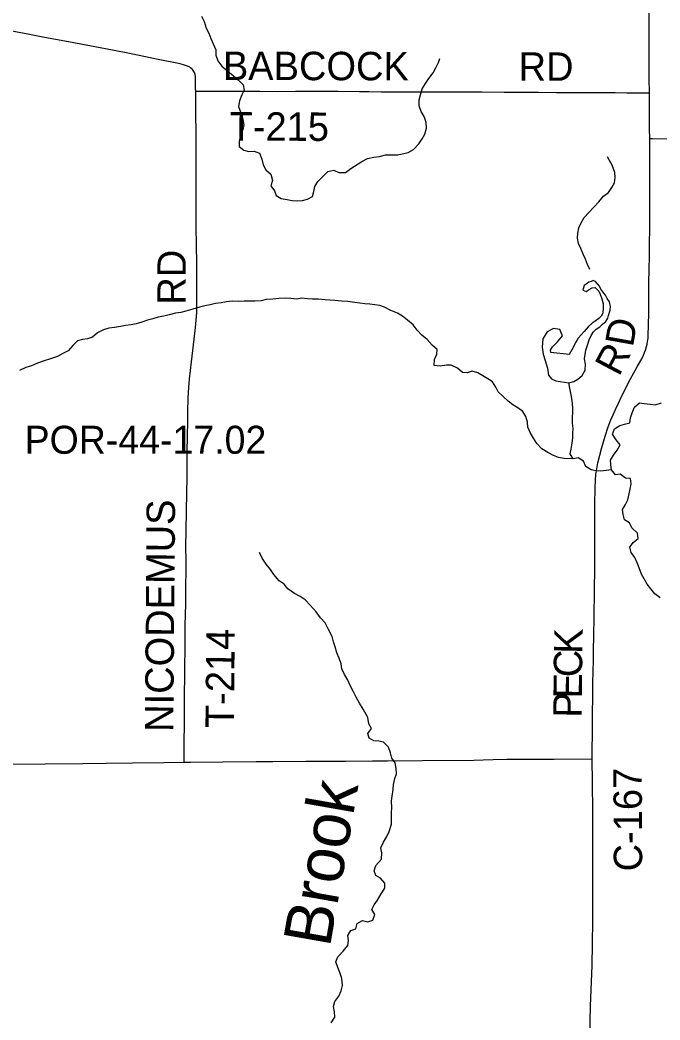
# Model space of a CAD drawing. Extents: x 0 to 34, y 0 to 22.
# Drawn here: x 4.121 to 7.317, y 9.413 to 14.409 of the extents above; entities that cross this region are included whole.
import ezdxf

# ---------------------------------------------------------------- set-up
doc = ezdxf.new("R2010")
doc.units = 0
for name, color, linetype in [('GM_X_County_Road', 7, 'Continuous'), ('GM_X_County_Road_Text', 7, 'Continuous'), ('GM_X_Minor_Lake', 7, 'Continuous'), ('GM_X_Minor_River', 7, 'Continuous'), ('GM_X_Minor_River_Text', 7, 'Continuous'), ('GM_X_Township_Road', 7, 'Continuous'), ('GM_X_Township_Road_Text', 7, 'Continuous'), ('SH_Text', 7, 'Continuous')]:
    doc.layers.add(name, color=color, linetype=linetype)

msp = doc.modelspace()

# ---------------------------------------------------------------- linework, layer by layer
at = {"layer": 'GM_X_County_Road'}
for points in [[(7.2639, 14.0452), (7.2636, 14.118), (7.2636, 14.1506), (7.2636, 14.1614), (7.2635, 14.1723), (7.2635, 14.2189), (7.2637, 14.2521), (7.2634, 14.3326), (7.2634, 14.3957), (7.2634, 14.4535)], [(7.2657, 13.8168), (7.2651, 13.8652), (7.2652, 13.896), (7.2645, 13.9254), (7.2643, 13.9627), (7.2641, 14.0125), (7.2641, 14.0311), (7.2639, 14.0452)], [(6.9784, 10.7179), (6.979, 10.7631), (6.9799, 10.8448), (6.9807, 10.9383), (6.9814, 11.0346), (6.9825, 11.0983), (6.9837, 11.1542), (6.9848, 11.2069), (6.985, 11.238), (6.9851, 11.2659), (6.9862, 11.3281), (6.988, 11.4306), (6.9886, 11.4601), (6.9897, 11.5237), (6.99, 11.5579), (6.9905, 11.5951), (6.9909, 11.6339), (6.9915, 11.7178), (6.992, 11.783), (6.9921, 11.8436), (6.9919, 11.87), (6.9922, 11.9041), (6.9924, 11.9662), (6.9924, 11.9924), (6.9925, 12.0186), (6.9927, 12.0424), (6.9933, 12.0706), (6.995, 12.1103), (6.9975, 12.1395), (7.0012, 12.1668), (7.0065, 12.1971), (7.016, 12.2347), (7.0265, 12.2729), (7.044, 12.3297), (7.0591, 12.3769), (7.0722, 12.4113), (7.0829, 12.4372), (7.0945, 12.4635), (7.1093, 12.4943), (7.1255, 12.5283), (7.1682, 12.6129), (7.2046, 12.6793), (7.226, 12.717), (7.2346, 12.735), (7.2398, 12.7472), (7.2446, 12.76), (7.2502, 12.7775), (7.253, 12.7899), (7.2554, 12.8026), (7.2566, 12.8118), (7.2573, 12.8193), (7.2578, 12.8258), (7.2581, 12.8322), (7.2583, 12.838), (7.2587, 12.8465), (7.2594, 12.8713), (7.2602, 12.9007), (7.2607, 12.9303), (7.2611, 12.9622), (7.2607, 13.0053), (7.2611, 13.0492), (7.2622, 13.0961), (7.2634, 13.1637), (7.2641, 13.2281), (7.2649, 13.2875), (7.2657, 13.3708), (7.2657, 13.4382), (7.266, 13.4904), (7.2662, 13.5367), (7.2658, 13.6189), (7.2663, 13.6648), (7.2663, 13.7534), (7.2657, 13.814), (7.2657, 13.8168)], [(2.8188, 10.6798), (2.8697, 10.68), (3.2053, 10.6832), (3.2658, 10.6842), (3.3326, 10.6853), (3.5691, 10.6851), (3.6275, 10.6855), (3.7629, 10.6872), (3.8468, 10.6884), (4.0192, 10.6911), (4.246, 10.6928), (4.4341, 10.6952), (4.5506, 10.6961), (4.6827, 10.6977), (4.8396, 10.6995), (4.9411, 10.701)], [(4.9411, 10.701), (4.9717, 10.7015), (5.1333, 10.703), (5.2996, 10.7041), (5.3835, 10.7043), (5.5482, 10.7056), (5.747, 10.7068), (5.8806, 10.7075), (5.9567, 10.708), (6.1291, 10.7094), (6.3877, 10.7118), (6.4333, 10.7127), (6.4833, 10.714), (6.5517, 10.7158), (6.6978, 10.717), (6.7879, 10.717), (6.9784, 10.7179)], [(6.9667, 9.3286), (6.9706, 9.4838), (6.973, 9.5614), (6.9765, 9.6458), (6.9777, 9.6832), (6.9805, 9.7958), (6.9822, 9.9093), (6.9822, 9.9403), (6.9822, 10.0692), (6.9815, 10.136), (6.9814, 10.1889), (6.9815, 10.2308), (6.9811, 10.3815), (6.981, 10.4561), (6.9798, 10.6005), (6.9784, 10.7179)]]:
    msp.add_lwpolyline(points, dxfattribs=at)
at = {"layer": 'GM_X_Minor_Lake'}
msp.add_line((6.7964, 12.6065), (6.8619, 12.5958), dxfattribs=at)
msp.add_lwpolyline([(6.8619, 12.5958), (6.8864, 12.6037), (6.9071, 12.6144), (6.9287, 12.6336), (6.9435, 12.6594), (6.9451, 12.6898), (6.94, 12.7164), (6.9471, 12.7592), (6.9554, 12.7849), (6.9636, 12.8106), (6.9738, 12.8335), (6.9849, 12.8508), (6.998, 12.8651), (7.0159, 12.8758), (7.03, 12.8893), (7.0468, 12.9037), (7.0571, 12.919), (7.0598, 12.9333), (7.068, 12.9599), (7.0697, 12.978), (7.0657, 13.0007), (7.0532, 13.0177), (7.0454, 13.0337), (7.031, 13.0516), (7.0214, 13.0638), (7.0155, 13.0789), (7.005, 13.0912), (6.9944, 13.1034), (6.984, 13.108), (6.9727, 13.1031), (6.9613, 13.0992), (6.9529, 13.0934), (6.9379, 13.0828), (6.9324, 13.0599), (6.9486, 13.0535), (6.9627, 13.0622), (6.9787, 13.0709), (6.9929, 13.073), (7.012, 13.0542), (7.0188, 13.0391), (7.0267, 13.0155), (7.0336, 12.9909), (7.0329, 12.97), (7.0312, 12.9443), (7.0238, 12.93), (7.0117, 12.9175), (6.9929, 12.904), (6.9778, 12.8953), (6.9581, 12.877), (6.9385, 12.8531), (6.9086, 12.8204), (6.8956, 12.7956), (6.877, 12.7612), (6.8641, 12.7373), (6.7721, 12.7486), (6.771, 12.759), (6.7803, 12.7762), (6.8056, 12.8021), (6.8299, 12.8309), (6.8172, 12.8621), (6.7859, 12.8684), (6.7539, 12.8509), (6.7316, 12.8155), (6.7282, 12.7746), (6.7334, 12.7405), (6.7432, 12.7084), (6.7559, 12.6705), (6.7601, 12.6355), (6.7755, 12.6167), (6.7964, 12.6065)], dxfattribs=at)
at = {"layer": 'GM_X_Minor_River'}
for points in [[(5.0273, 14.4276), (5.0399, 14.4021), (5.0497, 14.369), (5.0632, 14.3435), (5.074, 14.317), (5.0856, 14.2896), (5.0983, 14.2603), (5.0995, 14.2328), (5.1093, 14.2054), (5.1285, 14.1781), (5.1591, 14.1538), (5.1858, 14.1323), (5.2107, 14.1098), (5.2347, 14.0854), (5.2397, 14.0588), (5.2286, 14.035), (5.2166, 14.0054), (5.2112, 13.9778), (5.2239, 13.9447), (5.2327, 13.9201), (5.2378, 13.886), (5.2334, 13.8622), (5.2214, 13.8336), (5.2151, 13.8041), (5.2154, 13.7775), (5.2392, 13.7588), (5.263, 13.7525), (5.2904, 13.7537), (5.317, 13.7436), (5.3278, 13.7133), (5.3348, 13.6849), (5.3483, 13.6604), (5.3731, 13.6389), (5.3811, 13.6076), (5.3738, 13.581), (5.3911, 13.5565), (5.4008, 13.5319), (5.4247, 13.517), (5.455, 13.5117), (5.4797, 13.5072), (5.5062, 13.5056), (5.5318, 13.5068), (5.5563, 13.5138), (5.5808, 13.5274), (5.589, 13.5531), (5.5925, 13.5778), (5.6074, 13.6027), (5.6327, 13.6267), (5.658, 13.6517), (5.6873, 13.6587), (5.713, 13.6466), (5.7461, 13.648), (5.7733, 13.6673), (5.8279, 13.7021), (5.857, 13.7176), (5.8873, 13.7246), (5.9166, 13.7268), (5.9459, 13.7357), (5.9799, 13.7352), (6.0083, 13.7355), (6.0593, 13.7475), (6.0857, 13.763), (6.1119, 13.7899), (6.1287, 13.8148), (6.1426, 13.8396), (6.1517, 13.8692), (6.1486, 13.8976)], [(6.1486, 13.8976), (6.1388, 13.9269), (6.1243, 13.9524), (6.1145, 13.9798), (6.1151, 14.0102), (6.1205, 14.0359), (6.1287, 14.0645), (6.1464, 14.0912), (6.1632, 14.1171), (6.1837, 14.1448), (6.1967, 14.1697), (6.2115, 14.1964), (6.2179, 14.2165)], [(6.9663, 13.1619), (6.9547, 13.1884), (6.9449, 13.2139), (6.9333, 13.2394), (6.9216, 13.2677), (6.9099, 13.2932), (6.9059, 13.3197), (6.9075, 13.3435), (6.9119, 13.3701), (6.923, 13.3959), (6.9379, 13.4227), (6.9613, 13.4467), (6.9865, 13.4735), (7.0118, 13.5014), (7.0351, 13.5292), (7.0596, 13.5475), (7.0763, 13.5724), (7.0893, 13.5963), (7.0928, 13.6229), (7.0916, 13.6476), (7.0779, 13.6835), (7.0654, 13.708), (7.0547, 13.7259)], [(7.075, 12.1617), (7.0476, 12.1585), (7.0211, 12.1553), (6.9965, 12.1569), (6.9727, 12.1614), (6.946, 12.1791), (6.9353, 12.2046), (6.9086, 12.2224), (6.8831, 12.2173), (6.8377, 12.2187), (6.8101, 12.224), (6.7845, 12.2332), (6.7568, 12.2481), (6.7273, 12.2667), (6.7024, 12.293), (6.686, 12.3194), (6.6696, 12.3449), (6.6569, 12.3751), (6.6557, 12.4007), (6.6478, 12.4281), (6.6315, 12.4526), (6.6076, 12.4723), (6.5828, 12.4872), (6.5589, 12.505), (6.534, 12.5274), (6.5092, 12.5509), (6.4966, 12.5754), (6.4811, 12.6018), (6.4573, 12.6167), (6.4325, 12.6316), (6.4068, 12.6456), (6.3792, 12.6547), (6.3547, 12.6469), (6.3301, 12.6475), (6.3062, 12.6691), (6.2738, 12.6839), (6.2501, 12.6855), (6.2199, 12.6795), (6.1886, 12.6829), (6.1902, 12.7133), (6.2022, 12.7391), (6.2038, 12.7628), (6.1789, 12.7853), (6.155, 12.8135), (6.1282, 12.8341), (6.1042, 12.8604), (6.0841, 12.8858), (6.0554, 12.9101), (6.0306, 12.9298), (6.0067, 12.9447), (5.9725, 12.9585), (5.9411, 12.9743), (5.9173, 12.9826), (5.8936, 12.9861), (5.868, 12.9896), (5.8424, 12.9912), (5.7931, 12.9982), (5.758, 13.0025), (5.7267, 13.005), (5.6936, 13.0075), (5.6689, 13.01), (5.6443, 13.0107), (5.6111, 13.0151), (5.5808, 13.0147), (5.5571, 13.0163), (5.5277, 13.0198), (5.5032, 13.0147), (5.4738, 13.0172), (5.4454, 13.0188), (5.4132, 13.0175), (5.3829, 13.0143), (5.3498, 13.012), (5.3253, 13.006), (5.2931, 13.0047), (5.2401, 13.0041), (5.2117, 13.0028), (5.1823, 13.0043), (5.152, 13.0011), (5.1246, 12.9961), (5.0972, 12.9929), (5.0708, 12.9869), (5.0434, 12.9809), (5.0179, 12.9749), (4.9839, 12.9641), (4.949, 12.9551), (4.9244, 12.9482), (4.898, 12.9441), (4.8649, 12.9361), (4.8385, 12.9301), (4.8101, 12.9241), (4.7847, 12.9162), (4.7573, 12.9092), (4.7299, 12.8994), (4.7016, 12.8905), (4.6761, 12.8855), (4.6468, 12.8823), (4.6222, 12.8782), (4.5929, 12.8731), (4.5646, 12.869), (4.5372, 12.862), (4.508, 12.8465)], [(4.508, 12.8465), (4.4827, 12.8253), (4.4572, 12.8155), (4.4326, 12.8124), (4.4071, 12.8064), (4.3837, 12.7824), (4.3604, 12.7565), (4.3349, 12.7429), (4.3086, 12.7274), (4.2727, 12.7165), (4.2416, 12.7067), (4.2086, 12.6949), (4.1775, 12.6822), (4.1501, 12.6733), (4.1181, 12.6587)], [(6.8831, 12.2173), (6.8677, 12.2418), (6.8731, 12.2656), (6.8785, 12.2951), (6.882, 12.3198), (6.8826, 12.3445), (6.8833, 12.3683), (6.8802, 12.3948), (6.8799, 12.4242), (6.8815, 12.448), (6.8812, 12.4717), (6.8789, 12.5077), (6.8739, 12.5371), (6.8689, 12.5617), (6.8619, 12.5958)], [(7.3179, 11.5228), (7.2912, 11.5415), (7.272, 11.5669), (7.2537, 11.5913), (7.2373, 11.6168), (7.2247, 11.6413), (7.213, 11.6715), (7.2033, 11.698), (7.1907, 11.7235), (7.1734, 11.7489), (7.1664, 11.7754), (7.1832, 11.7993), (7.2086, 11.8186), (7.2045, 11.8461), (7.1767, 11.8724), (7.1651, 11.8969), (7.1403, 11.9128), (7.1324, 11.9383), (7.1302, 11.9639), (7.1451, 11.9878), (7.1562, 12.0126), (7.1625, 12.0412), (7.1679, 12.065), (7.1733, 12.0916), (7.1692, 12.1191), (7.1446, 12.1207), (7.1188, 12.1394), (7.0942, 12.1362), (7.075, 12.1617), (7.0719, 12.1863), (7.0707, 12.21), (7.0855, 12.2358), (7.1033, 12.2607), (7.1181, 12.2865), (7.0979, 12.3119), (7.0797, 12.3392), (7.0898, 12.3659), (7.1161, 12.3833), (7.1406, 12.3893), (7.1661, 12.3972), (7.1696, 12.421), (7.1788, 12.4458), (7.1899, 12.4744), (7.2142, 12.4965), (7.238, 12.493), (7.2673, 12.4905), (7.293, 12.486), (7.325, 12.4968)], [(5.7179, 9.6503), (5.7082, 9.6758), (5.6974, 9.7041), (5.7076, 9.7289), (5.7347, 9.7568), (5.7581, 9.7855), (5.7606, 9.8102), (5.7584, 9.8358), (5.7724, 9.8607), (5.7979, 9.8686), (5.8051, 9.8952), (5.8305, 9.9098), (5.8571, 9.9034), (5.8826, 9.9123), (5.8936, 9.9399), (5.8782, 9.9644), (5.8902, 9.9883), (5.907, 10.0122), (5.9237, 10.0428), (5.9423, 10.0715), (5.942, 10.0961), (5.9219, 10.1215), (5.8981, 10.1345), (5.8893, 10.1591), (5.8984, 10.1848), (5.9255, 10.2174), (5.9271, 10.2488), (5.923, 10.2734), (5.9369, 10.3011), (5.9536, 10.3298), (5.9637, 10.3555), (5.9756, 10.3917), (5.9763, 10.4202), (5.9769, 10.4496), (5.9785, 10.4734), (5.9762, 10.5075), (5.9797, 10.5322), (5.9851, 10.5646), (5.9867, 10.5902), (5.993, 10.6197), (6.0012, 10.6435), (5.999, 10.6692), (5.9949, 10.6976), (5.9785, 10.7221), (5.9707, 10.7486), (5.9609, 10.7769), (5.9369, 10.8013), (5.9132, 10.8067), (5.8886, 10.8083), (5.8648, 10.8204), (5.8579, 10.845), (5.8765, 10.8689), (5.8621, 10.8935), (5.8579, 10.9247), (5.8347, 10.9662), (5.8164, 10.9954), (5.799, 11.0266), (5.7864, 11.052), (5.7709, 11.0813), (5.7564, 11.1143), (5.7409, 11.1398), (5.7283, 11.1672), (5.7252, 11.1928), (5.7154, 11.2202), (5.7028, 11.2476), (5.6949, 11.2769), (5.6861, 11.3024), (5.6792, 11.3289), (5.6617, 11.3648), (5.6443, 11.3969), (5.6213, 11.4232), (5.6001, 11.4523), (5.5695, 11.4852), (5.5446, 11.5125), (5.5198, 11.5283), (5.4921, 11.5432), (5.4587, 11.5665), (5.4395, 11.591), (5.4147, 11.6078), (5.3888, 11.6388), (5.3715, 11.6633), (5.3494, 11.6905), (5.3301, 11.7197), (5.3175, 11.749), (5.3185, 11.7471)], [(5.6753, 9.3983), (5.693, 9.4279), (5.6918, 9.4545), (5.6858, 9.481), (5.6931, 9.5048), (5.7126, 9.5325), (5.7247, 9.5583), (5.731, 9.5859), (5.7287, 9.62), (5.7179, 9.6503)]]:
    msp.add_lwpolyline(points, dxfattribs=at)
at = {"layer": 'GM_X_Township_Road'}
for points in [[(4.9984, 14.0529), (4.9978, 14.0681), (4.9972, 14.096), (4.9973, 14.1039), (4.9967, 14.1291), (4.9949, 14.137), (4.9923, 14.1462), (4.9858, 14.1573), (4.9829, 14.1611), (4.9746, 14.1688), (4.9681, 14.1733), (4.9567, 14.1791), (4.9417, 14.1842), (4.9204, 14.1894), (4.8108, 14.2123), (4.6753, 14.24), (4.5821, 14.2577), (4.4938, 14.2755), (4.3625, 14.3005), (4.2433, 14.3223), (4.1593, 14.338), (4.0449, 14.3593), (3.9991, 14.3678), (3.9756, 14.3721)], [(4.9411, 10.701), (4.9411, 10.7182), (4.9411, 10.817), (4.9421, 10.8744), (4.9424, 10.9148), (4.9426, 10.9521), (4.9424, 11.0159), (4.9441, 11.1557), (4.9441, 11.2008), (4.9449, 11.2473), (4.9458, 11.3281), (4.9463, 11.384), (4.9482, 11.4928), (4.9491, 11.5845), (4.9498, 11.6544), (4.95, 11.7072), (4.9493, 11.7787), (4.9502, 11.8563), (4.9522, 11.9588), (4.9549, 12.1267), (4.956, 12.2479), (4.9574, 12.3333), (4.9588, 12.4016), (4.959, 12.4514), (4.961, 12.5212), (4.9635, 12.5724), (4.9669, 12.6141), (4.9764, 12.7021), (4.9905, 12.8146), (4.9977, 12.8733), (5.0012, 12.9089), (5.0034, 12.9478), (5.004, 12.9898), (5.0042, 13.0628), (5.0043, 13.1141), (5.0042, 13.1918), (5.0026, 13.2851), (5.0013, 13.3752), (5, 13.4746), (5.0002, 13.546), (4.9998, 13.6362), (5.0002, 13.7387), (5.0003, 13.8226), (5.0004, 13.8568), (4.9994, 13.9283), (4.9993, 13.992), (4.9989, 14.0386), (4.9984, 14.0529)], [(4.9984, 14.0529), (5.0111, 14.053), (5.037, 14.0534), (5.1363, 14.0537), (5.219, 14.0533), (5.3193, 14.0533), (5.4047, 14.0527), (5.4964, 14.053), (5.6222, 14.0535), (5.7092, 14.0532), (5.8164, 14.0524), (5.8645, 14.0516), (5.9251, 14.0507), (5.9811, 14.051), (6.0898, 14.0507), (6.1411, 14.0509), (6.1722, 14.0511), (6.305, 14.0506), (6.4267, 14.0499), (6.5391, 14.049), (6.621, 14.0479), (6.711, 14.0479), (6.7995, 14.0471), (6.9315, 14.0468), (6.963, 14.0465), (7.0291, 14.0465), (7.093, 14.0463), (7.1517, 14.0461), (7.2518, 14.0453), (7.2639, 14.0452)], [(7.2657, 13.8168), (7.2805, 13.8167), (7.4566, 13.8147), (7.7313, 13.8118), (7.7496, 13.8102), (7.7675, 13.8064), (7.776, 13.8033), (7.7858, 13.7991), (7.8003, 13.7906), (7.8131, 13.7819), (7.828, 13.771), (7.8358, 13.7647)]]:
    msp.add_lwpolyline(points, dxfattribs=at)

# ---------------------------------------------------------------- texts
at = {"layer": 'GM_X_County_Road_Text'}
for s, height, rotation, p in [('D', 0.142, 79.8842, (7.1815, 12.7714)), ('R', 0.142, 62.1013, (7.1116, 12.6237)), ('K', 0.142, 88.7286, (6.9291, 11.2413)), ('C', 0.142, 89.395, (6.9279, 11.1251)), ('E', 0.142, 89.4129, (6.9268, 11.0189)), ('P', 0.142, 89.4156, (6.9259, 10.9231)), ('C-167', 0.14205, 90.2751, (7.2285, 10.156))]:
    msp.add_text(s, height=height, rotation=rotation, dxfattribs=at).set_placement(p)
at = {"layer": 'GM_X_Minor_River_Text'}
msp.add_text('Brook', height=0.23682, rotation=79.9852, dxfattribs=at).set_placement((5.6677, 9.7717))
at = {"layer": 'GM_X_Township_Road_Text'}
for s, rotation, p in [('BABCOCK', 359.8583, (5.1337, 14.1096)), ('RD', 0, (6.6109, 14.1054)), ('T-215', 359.7181, (5.1672, 13.8072)), ('RD', 90, (4.9488, 12.9871)), ('NICODEMUS', 89.5401, (4.8862, 10.8521)), ('T-214', 89.4555, (5.1887, 10.871))]:
    msp.add_text(s, height=0.14205, rotation=rotation, dxfattribs=at).set_placement(p)
at = {"layer": 'SH_Text'}
msp.add_text('POR-44-17.02', height=0.14, dxfattribs=at).set_placement((4.1436, 12.242))

doc.saveas('drawing.dxf')
